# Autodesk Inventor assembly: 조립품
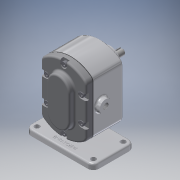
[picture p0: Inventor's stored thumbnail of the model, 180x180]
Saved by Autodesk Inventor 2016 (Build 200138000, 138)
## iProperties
Created: 2019-03
Part Number: 조립품
Document SubType Name: Weldment
Designer: 605-11
Weld Material: Welded Aluminum-6061
Author: 605-11
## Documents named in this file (11)
- C:\Users\605-11\Desktop\490307V1038\조립품.iam
- C:\Users\605-11\Desktop\490307V1038\490307V1038.ipt
- C:\Users\605-11\Desktop\490307V1038\서브축.ipt
- C:\Users\605-11\Desktop\490307V1038\메인축.ipt
- C:\Users\605-11\Desktop\490307V1038\키 6 x 6 x 18.ipt
- C:\Users\605-11\Desktop\490307V1038\스퍼기어.ipt
- C:\Users\605-11\Desktop\490307V1038\베어링부시.ipt
- C:\Users\605-11\Desktop\490307V1038\오일 실 16 28 7.ipt
- C:\Users\605-11\Desktop\490307V1038\커버.ipt
- C:\Users\605-11\Desktop\490307V1038\개스킷.ipt
- C:\Users\605-11\Desktop\490307V1038\볼트 M5.ipt
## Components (2 placed, 2 different names)
1. 490307V1038:1 — 각도:3, 각도:4, 각도:5, 각도:6
2. 개스킷:1
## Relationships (4: Angle 4)
- 각도:3 [Angle]: 490307V1038:1
- 각도:4 [Angle]: 490307V1038:1
- 각도:5 [Angle]: 490307V1038:1
- 각도:6 [Angle]: 490307V1038:1
